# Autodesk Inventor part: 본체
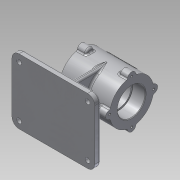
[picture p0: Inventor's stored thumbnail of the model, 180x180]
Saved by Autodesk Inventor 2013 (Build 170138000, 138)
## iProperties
Created: 2015-12
Part Number: 본체
Material: 알루미늄 6061
Document SubType Name: Modeling
Designer: Administrator
Density: 2.71 g/cm^3
Mass: 1167.11 g
Surface Area: 817.28 cm^2
Volume: 430.667 cm^3
Author: Administrator
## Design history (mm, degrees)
sketch "스케치1"
  geometry: L1 (-70, 55)-(70, 55); L2 (70, 55)-(70, -55); L3 (70, -55)-(-70, -55); L4 (-70, -55)-(-70, 55); 3 further points
  constraints: 8 end point, 2 midpoint, 2 parallel, 1 horizontal, 1 horizontal alignment, 1 perpendicular, 1 vertical alignment
extrude "돌출1" new body sketch "스케치1" distance "d3" = 10; taper "d4" = 0 deg
node "작업 평면1"
sketch "스케치2"
  geometry: L1 (0, 0)-(110, 0) reference; C1 r 37 at (55, 80); 1 further point
  constraints: 1 centre point
extrude "돌출2" join sketch "스케치2" distance "d8" = 85; taper "d9" = 0 deg
sketch "스케치3"
  geometry: 2 further points
hole "구멍1" sketch "스케치3" at (0, 0) diameter "d10" = 42; stored, may be unused: countersink angle "d14" = 90 deg, drill point angle "d16" = 0 deg; dims "d11" = 6, "d12" = 47, "d13" = 22, "d15" = 8
sketch "스케치4"
  geometry: C1 r 37 at (0, 0) reference; C2 r 23.5 at (0, 0); 1 further point
  constraints: 1 centre point, 1 coincident
  dimensions: "d17" = 47 diameter of C2
extrude "돌출3" cut sketch "스케치4" distance "d18" = 22; taper "d19" = 0 deg
sketch "스케치5"
  geometry: L1 (-70, 55)-(70, 55) reference; L2 (6, 37)-(14, 37); L3 (14, 37)-(14, -37); L4 (14, -37)-(6, -37); L5 (6, -37)-(6, 37); L6 (-70, -55)-(-70, 55) reference; 2 further points
  constraints: 8 end point, 2 parallel, 1 horizontal, 1 horizontal alignment, 1 midpoint, 1 perpendicular
extrude "돌출4" join sketch "스케치5" stored distance "d29" = 0; taper "d30" = 0 deg
sketch "스케치8"
  geometry: L1 (70, 10)-(-70, 10) reference; L2 (-32.5, 117)-(52.5, 117) reference; L3 (-32.5, 43)-(52.5, 43) reference; L4 (-15, 10)-(-10.948, 43); L5 (35, 10)-(30.948, 43); 1 further point
  constraints: 4 end point, 2 point on line
feature "리브1" sketch "스케치8" dims "d40" = 1, "d41" = 12, "d42" = 0, "d43" = 0, "d44" = 1, "d45" = 1
sketch "스케치9"
  geometry: L1 (-32.5, 43)-(52.5, 43) reference; L2 (70, 10)-(-70, 10) reference; L3 (30.948, 43)-(35, 10); L4 (-32.5, 117)-(52.5, 117) reference; 1 further point
  constraints: 2 end point, 2 point on line
feature "리브2" sketch "스케치9" dims "d50" = 1, "d51" = 12, "d52" = 0, "d53" = 0, "d54" = 1, "d55" = 1
sketch "스케치10"
  geometry: A1 r 7 centre (0, 37) between (6.969, 36.338) and (-6.969, 36.338); A2 r 7 centre (-37, 0) between (-36.338, 6.969) and (-36.338, -6.969); A3 r 7 centre (0, -37) between (-6.969, -36.338) and (6.969, -36.338); A4 r 7 centre (37, 0) between (36.338, -6.969) and (36.338, 6.969); 2 further points
  constraints: 8 point on circle, 4 centre point, 10 other
  dimensions: "d56" = 14 diameter of A1
extrude "돌출5" join sketch "스케치10" distance "d60" = 15; taper "d61" = 0 deg
sketch "스케치11"
  geometry: C1 r 23.5 at (55, 80) reference; A1 r 37 centre (55, 80) between (91.338, 86.969) and (61.969, 116.338) reference; A2 r 7 centre (55, 117) between (61.969, 116.338) and (48.031, 116.338) reference; A3 r 37 centre (55, 80) between (48.031, 116.338) and (18.662, 86.969) reference; A4 r 7 centre (18, 80) between (18.662, 86.969) and (18.662, 73.031) reference; A5 r 37 centre (55, 80) between (18.662, 73.031) and (48.031, 43.662) reference; A6 r 7 centre (55, 43) between (48.031, 43.662) and (61.969, 43.662) reference; A7 r 37 centre (55, 80) between (61.969, 43.662) and (91.338, 73.031) reference; A8 r 7 centre (92, 80) between (91.338, 73.031) and (91.338, 86.969) reference; 2 further points
  constraints: 1 coincident
hole "구멍2" sketch "스케치11" at (55, 117) diameter "d62" = 3.459; stored, may be unused: countersink angle "d66" = 90 deg, drill point angle "d68" = 118 deg; dims "d63" = 9, "d64" = 47, "d65" = 22, "d67" = 11
sketch "스케치12"
  geometry: C1 r 23.5 at (0, 0) reference; A1 r 7 centre (0, 37) between (6.969, 36.338) and (-6.969, 36.338); A2 r 7 centre (-37, 0) between (-36.338, 6.969) and (-36.338, -6.969); A3 r 7 centre (0, -37) between (-6.969, -36.338) and (6.969, -36.338); A4 r 7 centre (37, 0) between (36.338, -6.969) and (36.338, 6.969); 2 further points
  constraints: 8 point on circle, 4 centre point, 10 other
  dimensions: "d72" = 14 diameter of A1
extrude "돌출6" join sketch "스케치12" distance "d76" = 15; taper "d77" = 0 deg
sketch "스케치13"
  geometry: C1 r 23.5 at (-55, 80) reference; A1 r 37 centre (-55, 80) between (-91.338, 73.031) and (-61.969, 43.662) reference; A2 r 7 centre (-55, 43) between (-61.969, 43.662) and (-48.031, 43.662) reference; A3 r 37 centre (-55, 80) between (-48.031, 43.662) and (-18.662, 73.031) reference; A4 r 7 centre (-18, 80) between (-18.662, 73.031) and (-18.662, 86.969) reference; A5 r 37 centre (-55, 80) between (-18.662, 86.969) and (-48.031, 116.338) reference; A6 r 7 centre (-55, 117) between (-48.031, 116.338) and (-61.969, 116.338) reference; A7 r 37 centre (-55, 80) between (-61.969, 116.338) and (-91.338, 86.969) reference; A8 r 7 centre (-92, 80) between (-91.338, 86.969) and (-91.338, 73.031) reference; 2 further points
  constraints: 1 coincident
hole "구멍3" sketch "스케치13" at (-55, 117) diameter "d78" = 3.459; stored, may be unused: countersink angle "d82" = 90 deg, drill point angle "d84" = 118 deg; dims "d79" = 9, "d80" = 47, "d81" = 22, "d83" = 11
sketch "스케치14"
  geometry: L1 (70, 55)-(-70, 55) reference; C1 r 4 at (-58, 43); 1 further point
  constraints: 1 centre point
  dimensions: "d88" = 8 diameter of C1
extrude "돌출7" cut sketch "스케치14" distance "d91" = 20; taper "d92" = 0 deg
node "작업 평면2"
sketch "스케치16"
  geometry: L1 (55, 80)-(81.163, 106.163); A1 r 37 centre (55, 80) between (91.338, 86.969) and (61.969, 116.338) reference; 1 further point
  constraints: 2 end point, 1 point on circle
node "작업 평면3"
sketch "스케치17"
  geometry: L1 (42.5, 20.767)-(42.5, -20.767) reference; 2 further points
  constraints: 1 other
feature "엠보싱1" sketch "스케치17" dims "d96" = 0.5, "d97" = 0
chamfer "모따기1" distance "d98" = 1; stored, may be unused: second distance "d99" = 2, angle "d100" = 45 deg
fillet "모깎기1" dims "d101" = 12, "d102" = 3, "d103" = 0.3
fillet "모깎기2" dims "d104" = 3
node "솔리드1"
pattern_circular "원형 패턴1" dims angle "d70" = 360 deg
pattern_circular "원형 패턴2" dims angle "d86" = 360 deg
mirror "대칭1"
mirror "대칭2"
node "투영된 루프1"
node "투영된 루프2"
node "투영된 루프3"
other parameters: "d5" = -37.5, "d93" = -42.5
